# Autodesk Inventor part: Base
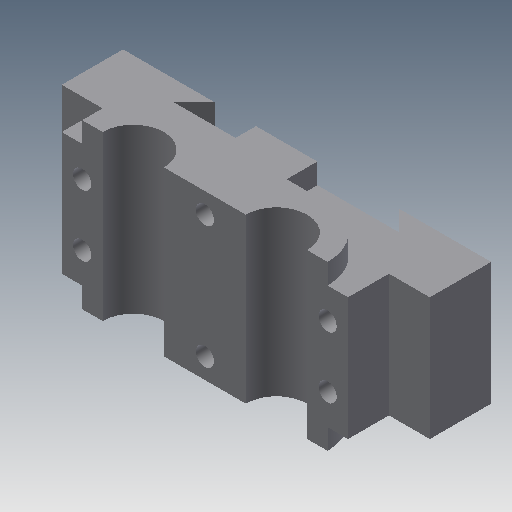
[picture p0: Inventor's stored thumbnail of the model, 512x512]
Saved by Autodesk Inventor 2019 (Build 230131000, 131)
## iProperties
Shininess: 77.0
Length Units: 11269
Angle Units: 11279
Time Units: 11290
Mass Units: 11283
Length Display Precision: 3
Angle Display Precision: 2
Created: 2002-02
Part Number: Base
Document SubType Name: Modeling
Designer: ***
Density: 1 g/cm^3
Material: Generic
Appearance: Default
Density: 0.0
Volumn: 0.0
Area: 0.0
PropertySet Name: Model Information
Control State: 0
Master: False
Checked Out: False
Author: ***
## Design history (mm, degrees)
sketch "Sketch2"
  geometry: L1 (-10.066, -1.263)-(24.934, -1.263); L2 (37.434, 11.237)-(32.434, 11.237); L3 (17.434, 11.237)-(-2.566, 11.237); L4 (-17.566, 11.237)-(-22.566, 11.237); A1 r 12.5 centre (-10.066, 11.237) between (-22.566, 11.237) and (-10.066, -1.263); A2 r 12.5 centre (24.934, 11.237) between (24.934, -1.263) and (37.434, 11.237); A3 r 7.5 centre (24.934, 11.237) between (17.434, 11.237) and (32.434, 11.237); A4 r 7.5 centre (-10.066, 11.237) between (-17.566, 11.237) and (-2.566, 11.237)
  constraints: 8 end point, 8 point on circle, 4 centre point, 3 horizontal, 3 parallel, 2 coincident, 2 equal radius, 2 tangent
  dimensions: "d0" = 12.5 radius of A1; "d1" = 7.5 radius of A4; "d2" = 35 distance of A1.centre A2.centre; "d3" = 12.5 distance between parallel lines of L3 L1
extrude "Extrusion1" new body sketch "Sketch2" stored distance "d4" = 40; taper "d5" = 0 deg
sketch "Sketch4"
  geometry: L1 (-27.566, 1.237)-(-37.566, 1.237); L2 (-37.566, 1.237)-(-37.566, -13.763); L3 (-37.566, -13.763)-(-15.066, -13.763); L4 (-15.066, -13.763)-(-20.066, -8.763); L5 (-20.066, -8.763)-(34.934, -8.763); L6 (34.934, -8.763)-(29.934, -13.763); L7 (29.934, -13.763)-(52.434, -13.763); L8 (52.434, -13.763)-(52.434, 1.237); L9 (52.434, 1.237)-(42.434, 1.237); L10 (24.934, -1.263)-(-10.066, -1.263); L11 (-17.566, 11.237)-(-22.566, 11.237) reference; L12 (37.434, 11.237)-(32.434, 11.237) reference; L13 (-22.566, 11.237)-(-27.566, 11.237); L14 (-27.566, 11.237)-(-27.566, 1.237); L15 (37.434, 11.237)-(42.434, 11.237); L16 (42.434, 11.237)-(42.434, 1.237); A1 r 12.5 centre (24.934, 11.237) between (24.934, -1.263) and (37.434, 11.237); A2 r 12.5 centre (-10.066, 11.237) between (-22.566, 11.237) and (-10.066, -1.263); A3 r 12.5 centre (24.934, 11.237) between (24.934, -1.263) and (37.434, 11.237) reference; A4 r 12.5 centre (-10.066, 11.237) between (-22.566, 11.237) and (-10.066, -1.263) reference
  constraints: 28 end point, 6 perpendicular, 5 equal length, 4 concentric, 4 parallel, 4 point on circle, 2 centre point, 2 collinear, 1 tangent
  dimensions: "d12" = 15 distance of L1.end L2.end; "d13" = 25 distance from line of L3 L11.end; "d14" = 90 distance between parallel lines of L2 L8; "d15" = 5 distance between parallel lines of L5 L7; "d16" = 22.5 distance of L2.end L3.end; "d24" = 5 distance of L12.start L15.end; "d25" = 15 distance from line of L8 L12.start
extrude "Extrusion3" join sketch "Sketch4" stored distance "d17" = 30; taper "d18" = 0 deg
sketch "Sketch5"
  geometry: L1 (-14.934, -1.263)-(0.066, -1.263); L2 (0.066, -1.263)-(0.066, -8.763); L3 (0.066, -8.763)-(-14.934, -8.763); L4 (-14.934, -8.763)-(-14.934, -1.263); L5 (10.066, -1.263)-(-24.934, -1.263) reference; 1 further point
  constraints: 8 end point, 2 parallel, 1 collinear, 1 horizontal, 1 perpendicular
  dimensions: "d19" = 7.5 distance of L1.end L2.end; "d20" = 15 distance of L2.end L3.end; "d21" = 15 distance from line of point (-29.934, -13.763) L4
extrude "Extrusion4" join sketch "Sketch5" distance "d22" = 40; taper "d23" = 0 deg
sketch "Sketch6"
  geometry: L1 (-5, -35)-(0, -35) reference; L2 (-5, -35)-(-5, -5) reference; 1 further point
  dimensions: "d26" = 7.5 distance from line of L1 point (0, -27.5); "d27" = 5 distance from line of L2 point (0, -27.5)
hole "Hole1" sketch "Sketch6" at (0, -27.5) diameter "d28" = 4.5; stored, may be unused: countersink angle "d32" = 82 deg, drill point angle "d34" = 0 deg; dims "d29" = 6, "d30" = 4, "d31" = 2, "d33" = 15
pattern_linear "Rectangular Pattern1" dims "d37" = 60, "d40" = 15
sketch "Sketch7"
  geometry: L1 (-20, -40)-(-20, -35) reference; L2 (0, -40)-(20, -40) reference; 1 further point
  dimensions: "d41" = 30 distance from line of L1 point (10, -35); "d42" = 5 distance from line of L2 point (10, -35)
hole "Hole2" sketch "Sketch7" at (10, -35) diameter "d43" = 4.5; stored, may be unused: countersink angle "d47" = 82 deg, drill point angle "d49" = 0 deg; dims "d44" = 6, "d45" = 4, "d46" = 2, "d48" = 15
pattern_linear "Rectangular Pattern2" dims "d52" = 30
body "Solid1"
